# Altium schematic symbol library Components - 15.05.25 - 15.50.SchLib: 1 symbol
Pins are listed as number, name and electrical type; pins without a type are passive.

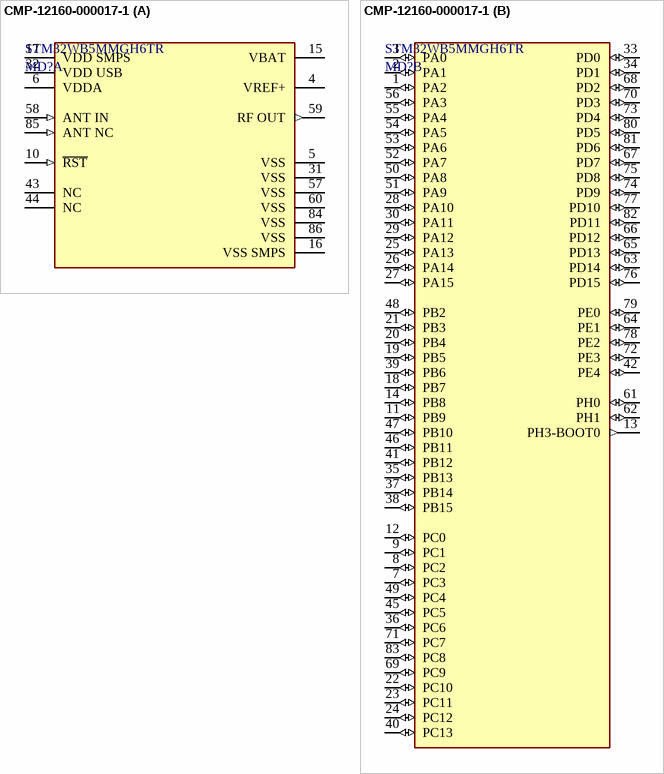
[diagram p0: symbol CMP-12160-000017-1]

## CMP-12160-000017-1
designator MD?, comment STM32WB5MMGH6TR
ULTRA-LOW-POWER DUAL CORE ARM CO
footprint FP-STM32WB5MMGH6TR-MFG
part A pins: 4 VREF+ (power), 5 VSS (power), 6 VDDA (power), 10 ~{RST} (in), 15 VBAT (power), 16 VSS SMPS (power), 17 VDD SMPS (power), 31 VSS (power), 32 VDD USB (power), 43 NC, 44 NC, 57 VSS (power), 58 ANT IN (in), 59 RF OUT (out), 60 VSS (power), 84 VSS (power), 85 ANT NC (in), 86 VSS (power)
part B pins: 1 PA2 (io), 2 PA1 (io), 3 PA0 (io), 7 PC3 (io), 8 PC2 (io), 9 PC1 (io), 11 PB9 (io), 12 PC0 (io), 13 PH3-BOOT0 (out), 14 PB8 (io), 18 PB7 (io), 19 PB5 (io), 20 PB4 (io), 21 PB3 (io), 22 PC10 (io), 23 PC11 (io), 24 PC12 (io), 25 PA13 (io), 26 PA14 (io), 27 PA15 (io), 28 PA10 (io), 29 PA12 (io), 30 PA11 (io), 33 PD0 (io), 34 PD1 (io), 35 PB13 (io), 36 PC6 (io), 37 PB14 (io), 38 PB15 (io), 39 PB6 (io), 40 PC13 (io), 41 PB12 (io), 42 PE4 (io), 45 PC5 (io), 46 PB11 (io), 47 PB10 (io), 48 PB2 (io), 49 PC4 (io), 50 PA8 (io), 51 PA9 (io), 52 PA7 (io), 53 PA6 (io), 54 PA5 (io), 55 PA4 (io), 56 PA3 (io), 61 PH0 (io), 62 PH1 (io), 63 PD14 (io), 64 PE1 (io), 65 PD13 (io), 66 PD12 (io), 67 PD7 (io), 68 PD2 (io), 69 PC9 (io), 70 PD3 (io), 71 PC7 (io), 72 PE3 (io), 73 PD4 (io), 74 PD9 (io), 75 PD8 (io), 76 PD15 (io), 77 PD10 (io), 78 PE2 (io), 79 PE0 (io), 80 PD5 (io), 81 PD6 (io), 82 PD11 (io), 83 PC8 (io)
